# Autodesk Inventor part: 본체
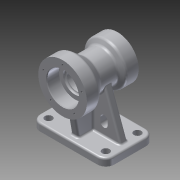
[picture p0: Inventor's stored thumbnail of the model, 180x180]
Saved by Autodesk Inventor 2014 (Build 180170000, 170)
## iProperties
Created: 2015-08
Part Number: 본체
Material: 알루미늄 6061
Document SubType Name: Modeling
Designer: SEC
Density: 2.71 g/cm^3
Appearance: 알루미늄 - 평지
Mass: 1062.8 g
Surface Area: 750.489 cm^2
Volume: 392.176 cm^3
Author: SEC
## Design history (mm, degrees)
sketch "스케치1"
  geometry: L1 (47, -40)-(-47, -40); L2 (-61, -26)-(-61, 26); L3 (-47, 40)-(47, 40); L4 (61, 26)-(61, -26); C1 r 6 at (47, -26); C2 r 6 at (-47, -26); C3 r 6 at (-47, 26); C4 r 6 at (47, 26); A1 r 14 centre (47, -26) between (47, -40) and (61, -26); A2 r 14 centre (-47, -26) between (-61, -26) and (-47, -40); A3 r 14 centre (-47, 26) between (-47, 40) and (-61, 26); A4 r 14 centre (47, 26) between (61, 26) and (47, 40); 6 further points
  constraints: 8 centre point, 8 end point, 8 point on circle, 8 tangent, 6 point on line, 4 coincident, 3 equal radius, 2 midpoint, 2 parallel, 1 horizontal, 1 horizontal alignment, 1 perpendicular, 1 vertical alignment
  dimensions: "d0" = 122 distance of point (-61, 40) point (61, 40); "d1" = 80 distance of point (-61, -40) point (-61, 40); "d2" = 14 radius of A1; "d3" = 12 diameter of C1; "d4" = 12 diameter of C2; "d5" = 12 diameter of C3; "d6" = 12 diameter of C4
extrude "돌출1" new body sketch "스케치1" distance "d7" = 12; taper "d8" = 0 deg
fillet "모깎기1" dims "d9" = 3
node "작업 평면1"
sketch "스케치8"
  geometry: L1 (-11, 12)-(63, 12) reference; L2 (66, 9)-(66, 0) reference; L3 (66, 0)-(-14, 0) reference; L4 (-14, 0)-(-14, 9) reference; L5 (56, 12)-(56, 63); L6 (-3.916, 12)-(-11.361, 54.226); L7 (56, 63)-(43.836, 69); L8 (43.836, 69)-(10.98, 67.65); L9 (10.98, 67.65)-(-11.361, 54.226); L10 (56, 12)-(56.285, 5.07); L11 (56.285, 5.07)-(-2.593, 4.5); L12 (-2.593, 4.5)-(-3.916, 12); A1 r 3 centre (-11, 9) between (-11, 12) and (-14, 9) reference; A2 r 3 centre (63, 9) between (66, 9) and (63, 12) reference; 1 further point
  constraints: 16 end point, 2 perpendicular, 2 point on line, 1 collinear
extrude "돌출2" join sketch "스케치8" stored distance "d92" = 12; taper "d93" = 0 deg
node "작업 평면2"
sketch "스케치9"
  geometry: L1 (-11, 12)-(41, 12) reference; L2 (41, 12)-(41, 68.267) reference; L3 (53, 68.267)-(53, 12) reference; L4 (53, 12)-(105, 12) reference; L5 (108, 9)-(108, 0) reference; L6 (108, 0)-(-14, 0) reference; L7 (-14, 0)-(-14, 9) reference; L8 (98, 12)-(71.141, 85.795); L9 (-4.245, 11.383)-(22.354, 85.272); L10 (-4.245, 11.383)-(-6.059, 6.342); L11 (-6.059, 6.342)-(100.73, 4.5); L12 (100.73, 4.5)-(98, 12); L13 (22.354, 85.272)-(38.51, 70.192); L14 (38.51, 70.192)-(56.29, 69.885); L15 (56.29, 69.885)-(71.141, 85.795); L16 (41, 68.267)-(53, 68.267) reference; A1 r 3 centre (-11, 9) between (-11, 12) and (-14, 9) reference; A2 r 3 centre (105, 9) between (108, 9) and (105, 12) reference; 1 further point
  constraints: 16 end point, 2 collinear, 1 parallel, 1 perpendicular, 1 point on line
extrude "돌출3" join sketch "스케치9" stored distance "d96" = 12; taper "d97" = 0 deg
fillet "모깎기5" dims "d98" = 3
fillet "모깎기6" dims "d99" = 3
node "작업 평면3"
sketch "스케치10"
  geometry: L1 (43.836, 69)-(56, 63) reference; L2 (56, 63)-(56, 15) reference; L3 (59, 12)-(63, 12) reference; L4 (66, 9)-(66, 0) reference; L5 (66, 0)-(-14, 0) reference; L6 (-14, 0)-(-14, 9) reference; L7 (-11, 12)-(-7.491, 12) reference; L8 (-4.536, 15.521)-(-11.361, 54.226) reference; L9 (-11.361, 54.226)-(10.98, 67.65) reference; L10 (10.98, 67.65)-(20, 68.021) reference; L11 (20, 68.021)-(20, 70.045) reference; L12 (20, 70.045)-(32, 70.045) reference; L13 (32, 70.045)-(32, 68.514) reference; L14 (32, 68.514)-(43.836, 69) reference; L15 (66, 0)-(66, 90); L16 (66, 90)-(-24, 90); L17 (66, 90)-(66, 125); L18 (66, 125)-(46, 125); L19 (46, 125)-(40.804, 116); L20 (40.804, 116)-(12.685, 116); L21 (12.685, 116)-(-4, 130); L22 (-4, 130)-(-24, 130); L23 (-24, 130)-(-24, 90); A1 r 3 centre (59, 15) between (56, 15) and (59, 12) reference; A2 r 3 centre (63, 9) between (66, 9) and (63, 12) reference; A3 r 3 centre (-11, 9) between (-11, 12) and (-14, 9) reference; A4 r 3 centre (-7.491, 15) between (-7.491, 12) and (-4.536, 15.521) reference; 1 further point
  constraints: 18 end point, 4 parallel, 3 perpendicular
  dimensions: "d101" = 90 distance of L4.end L15.end; "d102" = 90 distance of L15.end L16.end; "d103" = 80 diameter of L22 L16; "d104" = 70 diameter of L18 L16; "d105" = 60 deg angle of L19 L20; "d106" = 40 deg angle of L21 L16; "d107" = 20 distance of L17.end L18.end; "d108" = 20 distance of L21.end L22.end; "d109" = 52 diameter of L20 L16
revolve "회전2" sketch "스케치10" stored, may be unused: angle "d110" = 90 deg
fillet "모깎기8" dims "d111" = 5
fillet "모깎기9" dims "d112" = 3
sketch "스케치11" dims "d113" = 66
  geometry: C1 r 40 at (0, 0) reference; 3 further points
  constraints: 1 coincident, 1 vertical alignment, 2 other
hole "구멍5" sketch "스케치11" at (0, 33) diameter "d114" = 3.242; stored, may be unused: countersink angle "d118" = 82 deg, drill point angle "d120" = 118 deg; dims "d115" = 10, "d116" = 3.023, "d117" = 17, "d119" = 13
sketch "스케치12" dims "d124" = 54
  geometry: C1 r 35 at (0, 0) reference; 3 further points
  constraints: 1 coincident, 1 vertical alignment, 2 other
hole "구멍6" sketch "스케치12" at (0, 27) diameter "d125" = 3.242; stored, may be unused: countersink angle "d129" = 82 deg, drill point angle "d131" = 118 deg; dims "d126" = 10, "d127" = 3.023, "d128" = 17, "d130" = 13
sketch "스케치13"
  geometry: C1 r 40 at (0, 0) reference; 1 further point
hole "구멍7" sketch "스케치13" at (0, 0) diameter "d135" = 38; stored, may be unused: countersink angle "d139" = 82 deg, drill point angle "d141" = 0 deg; dims "d136" = 10, "d137" = 52, "d138" = 20, "d140" = 23
sketch "스케치14"
  geometry: C1 r 35 at (0, 0) reference; 1 further point
hole "구멍8" sketch "스케치14" at (0, 0) diameter "d142" = 32; stored, may be unused: countersink angle "d146" = 82 deg, drill point angle "d148" = 0 deg; dims "d143" = 10, "d144" = 40, "d145" = 17, "d147" = 90
chamfer "모따기2" distance "d149" = 1; stored, may be unused: second distance "d150" = 2, angle "d151" = 45 deg
fillet "모깎기10" dims "d152" = 0.3
fillet "모깎기11" dims "d153" = 3
sketch "스케치16"
  geometry: L1 (38, 62.432)-(38, 15) reference; L2 (47, 0)-(23, 0); L3 (23, 0)-(23, 30); L4 (29, 30)-(29.002, 35.998); L5 (17.002, 36.002)-(17, 30.002); A1 r 6 centre (23, 30) between (23.002, 36) and (29, 30); A2 r 6 centre (23.002, 36) between (29.002, 35.998) and (17.002, 36.002)
  constraints: 8 end point, 5 point on circle, 3 tangent, 2 centre point, 2 perpendicular, 1 coincident
  dimensions: "d163" = 24 distance of L2.start L2.end; "d164" = 30 distance of L2.end L3.end; "d165" = 12 diameter of A1; "d166" = 12 diameter of A2
extrude "돌출5" cut sketch "스케치16" stored distance "d167" = 12; taper "d168" = 0 deg
sketch "스케치17"
  geometry: L1 (5.82, 47.952)-(7.209, 47.952) reference; L2 (-17, 62.432)-(-14.504, 62.432) reference; L3 (-17, 15)-(-17, 62.432) reference; L4 (-17, 15)-(1.398, 15) reference; L5 (1.398, 15)-(7.209, 47.952) reference; L6 (24, 50.453)-(12.111, 50.453) reference; L7 (24, 63.675)-(24, 50.453) reference; L8 (4.3, 64.702)-(23, 64.702) reference; L9 (4, 71.972)-(4, 65.01) reference; L10 (-49, 75.168)-(1, 75.168) reference; L11 (-49, 71.236)-(-49, 75.168) reference; L12 (-65, 70.921)-(-49.3, 70.921) reference; L13 (-66, 55.518)-(-66, 69.875) reference; L14 (-57.863, 55.518)-(-66, 55.518) reference; L15 (-53, 53.081)-(-48.887, 53.081) reference; L16 (-37.917, 62.432)-(-35, 62.432) reference; L17 (-35, 62.432)-(-35, 15) reference; L18 (-53, 15)-(-35, 15) reference; L19 (-53, 53.081)-(-53, 15) reference; L20 (6.675, 12)-(11, 12) reference; L21 (14, 9)-(14, 0) reference; L22 (14, 0)-(-66, 0) reference; L23 (-66, 0)-(-66, 9) reference; L24 (-63, 12)-(-58.196, 12) reference; L25 (5.82, 129.547)-(24, 129.547) reference; L26 (24, 129.547)-(24, 116.325) reference; L27 (23, 115.298)-(4.3, 115.298) reference; L28 (4, 114.99)-(4, 108.028) reference; L29 (1, 104.832)-(-49, 104.832) reference; L30 (-49, 104.832)-(-49, 108.764) reference; L31 (-49.3, 109.079)-(-65, 109.079) reference; L32 (-66, 110.125)-(-66, 124.482) reference; L33 (-66, 124.482)-(-48.887, 124.482) reference; L34 (-37.917, 115.298)-(-14.504, 115.298) reference; L35 (-66, 0)-(-40, 0); L36 (-40, 0)-(-40, 36); A1 r 3 centre (11, 9) between (14, 9) and (11, 12) reference; A2 r 3 centre (-63, 9) between (-63, 12) and (-66, 9) reference; 10 further points
  constraints: 4 end point, 1 coincident, 1 perpendicular, 1 point on line, 27 other
  dimensions: "d169" = 26 distance of L22.end L35.end; "d170" = 36 distance of L35.end L36.end
feature "엠보싱1" sketch "스케치17" dims "d0" = 122, "d1" = 80, "d2" = 14, "d3" = 12, "d4" = 12, "d5" = 12, "d6" = 12, "d171" = 0.5, "d172" = 0
node "솔리드1"
pattern_circular "원형 패턴3" dims angle "d122" = 360 deg
pattern_circular "원형 패턴4" dims angle "d133" = 360 deg
mirror "대칭1"
node "절단 모서리 투영3"
node "절단 모서리 투영4"
node "절단 모서리 투영5"
node "절단 모서리 투영6"
